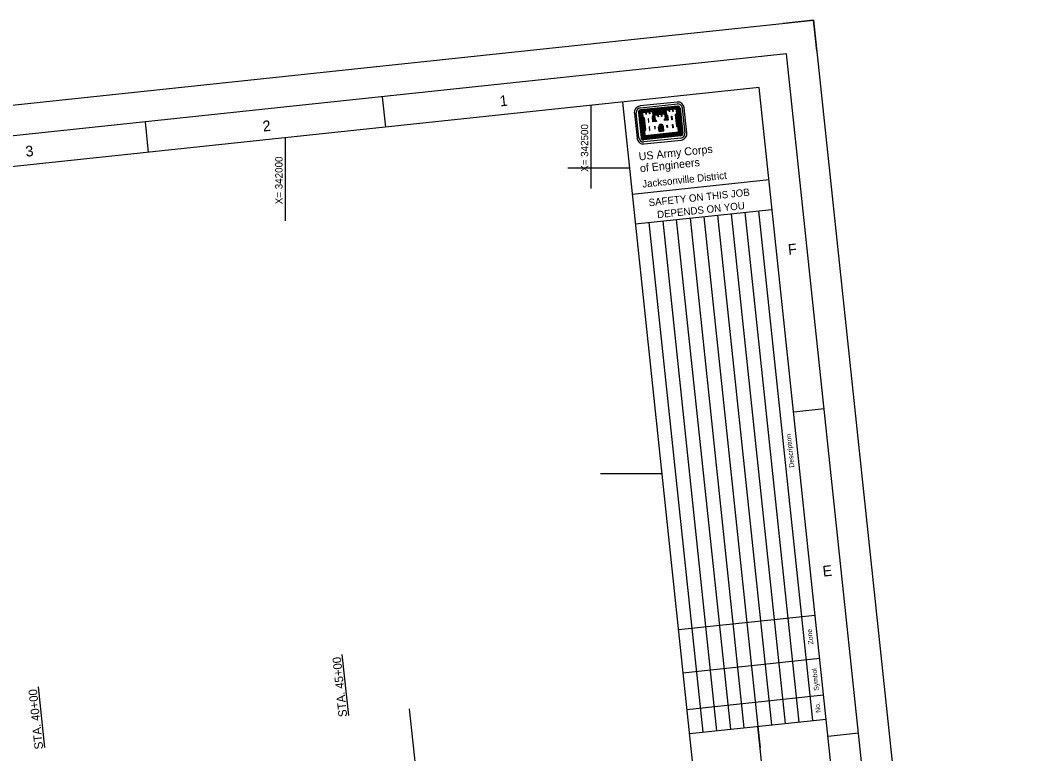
# Model space of a CAD drawing. Extents: x 338488 to 343222, y 1183896 to 1187741.
# Drawn here: x 341566 to 343222, y 1186542 to 1187741 of the extents above; entities that cross this region are included whole.
import ezdxf

# ---------------------------------------------------------------- set-up
doc = ezdxf.new("R2010")
doc.units = 0
for name, color, linetype in [('G-ANNO-NPLT', 7, 'Continuous'), ('G-ANNO-TEXT-LOGO', 7, 'Continuous'), ('G-ANNO-TEXT-TTLB', 7, 'Continuous'), ('G-ANNO-TTLB', 7, 'Continuous'), ('V-ALGN-TEXT', 7, 'Continuous'), ('V-ANNO-MATC', 7, 'Continuous'), ('V-TOPO-COOR-STAT', 7, 'Continuous')]:
    doc.layers.add(name, color=color, linetype=linetype)

msp = doc.modelspace()

# ---------------------------------------------------------------- linework, layer by layer
at = {"layer": 'G-ANNO-NPLT'}
msp.add_lwpolyline([(338488.3, 1187277.4), (342863.7, 1187741.2), (343222.1, 1184360.2), (338846.6, 1183896.4)], close=True, dxfattribs=at)
msp.add_lwpolyline([(342869, 1187691.5), (342863.7, 1187741.2), (342814, 1187736)], dxfattribs=at)
at = {"layer": 'G-ANNO-TEXT-LOGO'}
for p, q in [((342640.4, 1187607.6), (342580, 1187601.2)), ((342580.3, 1187598), (342640.8, 1187604.4)), ((342641.1, 1187601), (342580.7, 1187594.6)), ((342641.2, 1187600.1), (342580.8, 1187593.7)), ((342641.3, 1187599.2), (342580.9, 1187592.8)), ((342641.4, 1187598.4), (342580.9, 1187592)), ((342641.5, 1187597.5), (342581, 1187591.1)), ((342602.1, 1187592.5), (342620.6, 1187594.5)), ((342640.4, 1187596.8), (342644.6, 1187557.2)), ((342641.2, 1187596.9), (342645.5, 1187556.4)), ((342642.1, 1187597), (342646.4, 1187556.2)), ((342643, 1187597.1), (342647.3, 1187556.3)), ((342643.7, 1187597.2), (342648.1, 1187556.4)), ((342644.6, 1187597.3), (342649, 1187556.5)), ((342645.5, 1187597.3), (342649.9, 1187556.6)), ((342648.9, 1187597.7), (342653.2, 1187556.9)), ((342656.5, 1187557.3), (342652.2, 1187598.1)), ((342570.5, 1187589.4), (342574.8, 1187548.6)), ((342578, 1187549), (342573.6, 1187589.7)), ((342577.1, 1187590.1), (342581.4, 1187549.3)), ((342578, 1187590.2), (342582.3, 1187549.4)), ((342578.8, 1187590.3), (342583.1, 1187549.5)), ((342579.7, 1187590.4), (342584, 1187549.6)), ((342580.6, 1187590.5), (342584.9, 1187549.7)), ((342581.5, 1187590.6), (342585.8, 1187550.1)), ((342582.3, 1187590.6), (342586.5, 1187551.1)), ((342583.9, 1187582.1), (342586.1, 1187561.2)), ((342584.9, 1187581.3), (342586.9, 1187562.3)), ((342602.2, 1187591.6), (342620.7, 1187593.6)), ((342602.3, 1187590.9), (342620.8, 1187592.8)), ((342602.4, 1187590), (342620.9, 1187591.9)), ((342602.5, 1187589.1), (342621, 1187591)), ((342602.6, 1187588.3), (342621.1, 1187590.2)), ((342602.6, 1187587.4), (342621.1, 1187589.3)), ((342639.8, 1187587.1), (342641.8, 1187568.1)), ((342640.6, 1187588), (342642.8, 1187567.3)), ((342610.9, 1187559.6), (342610.2, 1187566.3)), ((342611.7, 1187559.7), (342611, 1187566.3)), ((342612.6, 1187559.8), (342611.9, 1187566.4)), ((342613.5, 1187559.9), (342612.8, 1187566.5)), ((342614.3, 1187559.9), (342613.6, 1187566.6)), ((342615.5, 1187560.1), (342614.8, 1187566.7)), ((342616.3, 1187560.2), (342615.6, 1187566.8)), ((342617.2, 1187560.3), (342616.5, 1187566.9)), ((342618.1, 1187560.3), (342617.4, 1187567)), ((342618.9, 1187560.4), (342618.2, 1187567.1)), ((342645.9, 1187555.6), (342585.5, 1187549.1)), ((342646, 1187554.8), (342585.6, 1187548.4)), ((342646.1, 1187553.9), (342585.7, 1187547.5)), ((342645.5, 1187556.4), (342585.8, 1187550.1)), ((342646.2, 1187553), (342585.8, 1187546.6)), ((342646.3, 1187552.2), (342585.8, 1187545.8)), ((342646.7, 1187548.7), (342586.2, 1187542.3)), ((342644.6, 1187557.2), (342586.5, 1187551.1)), ((342586.6, 1187539), (342647, 1187545.4)), ((342610.9, 1187559.6), (342618.9, 1187560.4))]:
    msp.add_line(p, q, dxfattribs=at)
for points in [[(342583, 1187590.7), (342583.8, 1187582.9), (342585.7, 1187581.4), (342587.7, 1187562.4), (342586.2, 1187560.4), (342587.1, 1187551.7), (342643.8, 1187557.7), (342642.9, 1187566.4), (342640.9, 1187568), (342638.9, 1187587), (342640.5, 1187588.9), (342639.7, 1187596.7), (342632.2, 1187595.9), (342626.4, 1187595.3), (342621.1, 1187594.8), (342621.9, 1187586.9), (342624, 1187585.4), (342624.7, 1187578.4), (342620.5, 1187578), (342620.5, 1187578.7), (342622.1, 1187580.7), (342621.2, 1187588.4), (342613.8, 1187587.6), (342608, 1187587), (342602.7, 1187586.5), (342603.6, 1187578.7), (342605.5, 1187577.1), (342605.6, 1187576.4), (342601.4, 1187576), (342600.7, 1187582.9), (342602.3, 1187584.8), (342601.5, 1187592.7), (342594, 1187591.9), (342588.3, 1187591.3), (342583, 1187590.7)], [(342583.9, 1187589.9), (342584.6, 1187583.3), (342586.6, 1187581.7), (342588.6, 1187562.1), (342587, 1187560.1), (342587.8, 1187552.7), (342642.9, 1187558.6), (342642.1, 1187565.9), (342640.1, 1187567.5), (342638, 1187587.2), (342639.7, 1187589.2), (342639, 1187595.7), (342633.6, 1187595.2), (342633.9, 1187592.1), (342633.4, 1187592), (342633.1, 1187595.1), (342627.8, 1187594.6), (342628.2, 1187591.5), (342627.8, 1187591.4), (342627.4, 1187594.5), (342622.1, 1187594), (342622.8, 1187587.4), (342624.7, 1187585.8), (342625.6, 1187577.7), (342619.8, 1187577.1), (342619.6, 1187579), (342621.2, 1187581), (342620.5, 1187587.6), (342615.2, 1187587), (342615.5, 1187583.9), (342615.1, 1187583.9), (342614.8, 1187586.9), (342609.4, 1187586.4), (342609.7, 1187583.3), (342609.2, 1187583.2), (342608.9, 1187586.3), (342603.6, 1187585.8), (342604.3, 1187579.2), (342606.3, 1187577.6), (342606.5, 1187575.7), (342600.7, 1187575.1), (342599.9, 1187583.2), (342601.5, 1187585.1), (342600.8, 1187591.7), (342595.5, 1187591.1), (342595.8, 1187588.1), (342595.3, 1187588), (342595, 1187591.1), (342589.6, 1187590.5), (342590, 1187587.4), (342589.6, 1187587.4), (342589.2, 1187590.5), (342583.9, 1187589.9)], [(342593.2, 1187580.1), (342593.8, 1187574.4), (342594.4, 1187574.4), (342593.8, 1187580.2), (342593.2, 1187580.1)], [(342602.1, 1187583.2), (342601.6, 1187582.6), (342602.2, 1187577), (342604.1, 1187577.2), (342602.7, 1187578.3), (342602.2, 1187583.3)], [(342622.6, 1187585.4), (342623.1, 1187584.9), (342623.7, 1187579.2), (342621.9, 1187579.1), (342623, 1187580.5), (342622.5, 1187585.4)], [(342631.8, 1187584.2), (342632.5, 1187578.5), (342632, 1187578.4), (342631.3, 1187584.2), (342631.8, 1187584.2)], [(342594.6, 1187566.9), (342595.2, 1187561), (342595.8, 1187561.1), (342595.2, 1187567), (342594.6, 1187566.9)], [(342603.7, 1187567.9), (342604.1, 1187563.8), (342604.6, 1187563.9), (342604.2, 1187567.9), (342603.7, 1187567.9)], [(342624.2, 1187570), (342624.6, 1187566), (342624.1, 1187565.9), (342623.7, 1187570), (342624.2, 1187570)], [(342633.2, 1187571), (342633.9, 1187565.1), (342633.4, 1187565.1), (342632.7, 1187571), (342633.2, 1187571)]]:
    msp.add_lwpolyline(points, dxfattribs=at)
for centre, major_axis, start_param, end_param in [((342581.1, 1187590.5), (10.7, 1.1), 1.57078, 3.141576), ((342581.1, 1187590.5), (7.45, 0.79), 1.57078, 3.141576), ((342581.1, 1187590.5), (4, 0.42), 1.57078, 3.141576), ((342641.5, 1187596.9), (10.7, 1.1), 6.283169, 7.853965), ((342641.5, 1187596.9), (7.45, 0.79), 6.28317, 7.853966), ((342641.5, 1187596.9), (4, 0.42), 6.283169, 7.853965), ((342641.5, 1187596.9), (3.13, 0.33), 6.283169, 7.853965), ((342641.5, 1187596.9), (2.27, 0.24), 6.283169, 7.853965), ((342641.5, 1187596.9), (1.41, 0.15), 6.283169, 7.853965), ((342641.5, 1187596.9), (0.543, 0.058), 6.283169, 7.853965), ((342581.1, 1187590.5), (3.13, 0.33), 1.57078, 3.141576), ((342581.1, 1187590.5), (2.27, 0.24), 1.57078, 3.141576), ((342581.1, 1187590.5), (1.41, 0.15), 1.57078, 3.141576), ((342581.1, 1187590.5), (0.543, 0.058), 1.57078, 3.141576), ((342615.7, 1187566.4), (-5.52, -0.59), 4.985832, 6.214359), ((342615.7, 1187566.4), (-4.66, -0.49), 4.947465, 6.21436), ((342615.7, 1187566.4), (-3.8, -0.4), 4.947465, 6.21436), ((342615.7, 1187566.4), (-2.93, -0.31), 4.947465, 6.21436), ((342612.7, 1187566.1), (2.07, 0.22), 0.068794, 1.335689), ((342612.7, 1187566.1), (2.93, 0.31), 0.068794, 1.335689), ((342612.7, 1187566.1), (3.8, 0.4), 0.068795, 1.335689), ((342612.7, 1187566.1), (4.66, 0.49), 0.068795, 1.335689), ((342615.7, 1187566.4), (-2.07, -0.22), 4.947465, 6.214359), ((342612.7, 1187566.1), (5.52, 0.59), 0.068795, 1.29842), ((342585.4, 1187549.7), (-10.7, -1.1), 6.28317, 7.853966), ((342585.4, 1187549.7), (-7.45, -0.79), 6.28317, 7.853966), ((342585.4, 1187549.7), (-4, -0.42), 6.28317, 7.853966), ((342585.4, 1187549.7), (-3.13, -0.33), 6.28317, 7.853966), ((342585.4, 1187549.7), (-2.27, -0.24), 6.28317, 7.853966), ((342585.4, 1187549.7), (-1.41, -0.15), 6.28317, 7.853966), ((342585.4, 1187549.7), (-0.543, -0.058), 6.28317, 7.853966), ((342645.8, 1187556.1), (0.543, 0.058), 4.712373, 6.28317), ((342645.8, 1187556.1), (1.41, 0.15), 4.712373, 6.28317), ((342645.8, 1187556.1), (2.27, 0.24), 4.712373, 6.28317), ((342645.8, 1187556.1), (4, 0.42), 4.712373, 6.28317), ((342645.8, 1187556.1), (3.13, 0.33), 4.712373, 6.28317), ((342645.8, 1187556.1), (-7.45, -0.79), 1.570781, 3.141577), ((342645.8, 1187556.1), (10.7, 1.1), 4.712373, 6.28317)]:
    msp.add_ellipse(centre, major_axis=major_axis, ratio=0.99964, start_param=start_param, end_param=end_param, dxfattribs=at)
at = {"layer": 'G-ANNO-TTLB'}
for p, q in [((342158, 1187616.1), (342163.3, 1187566.4)), ((342551, 1187607.5), (342888.4, 1184425.4)), ((341770.2, 1187575), (341775.4, 1187525.3)), ((342567, 1187457.1), (342790.8, 1187480.9)), ((342571.6, 1187408.2), (342795.3, 1187431.9)), ((342773.4, 1187429.6), (342861.7, 1186596.4)), ((342616.8, 1187413), (342705.1, 1186579.8)), ((342639.1, 1187415.4), (342727.5, 1186582.1)), ((342661.5, 1187417.8), (342749.8, 1186584.5)), ((342683.9, 1187420.1), (342772.2, 1186586.9)), ((342706.3, 1187422.5), (342794.6, 1186589.3)), ((342728.6, 1187424.9), (342817, 1186591.6)), ((342751, 1187427.3), (342839.3, 1186594)), ((342594.4, 1187410.6), (342682.7, 1186577.4)), ((342880.8, 1187106), (342831.1, 1187100.7)), ((342642.5, 1186745.1), (342866.2, 1186768.8)), ((342650, 1186674.4), (342873.7, 1186698.1)), ((342656.3, 1186614.7), (342880.1, 1186638.4)), ((342660.5, 1186575.1), (342884.3, 1186598.8)), ((342862.3, 1185732.1), (342772.4, 1186586.9)), ((342772.4, 1186586.9), (342776.1, 1186551.7)), ((342937, 1186575.7), (342887.3, 1186570.4))]:
    msp.add_line(p, q, dxfattribs=at)
for points in [[(338891.1, 1183951.4), (343167.1, 1184404.6), (342819.3, 1187686.2), (338543.3, 1187233)], [(342774.8, 1187631.3), (338672.8, 1187196.4), (339010.1, 1184014.3), (343112.1, 1184449.1)]]:
    msp.add_lwpolyline(points, close=True, dxfattribs=at)
at = {"layer": 'V-ALGN-TEXT'}
for p, q in [((342103.3, 1186604.8), (342092.8, 1186704.2)), ((341606.1, 1186552.1), (341595.6, 1186651.5))]:
    msp.add_line(p, q, dxfattribs=at)
at = {"layer": 'V-ANNO-MATC'}
msp.add_line((342339.8, 1185322.5), (342202.8, 1186615.3), dxfattribs=at)
at = {"layer": 'V-TOPO-COOR-STAT'}
for p, q in [((342500, 1187466.4), (342500, 1187602.1)), ((342000, 1187413.4), (342000, 1187549.1)), ((342461.9, 1187500), (342562.4, 1187500)), ((342514.9, 1187000), (342615.4, 1187000))]:
    msp.add_line(p, q, dxfattribs=at)

# ---------------------------------------------------------------- texts
at = {"layer": 'G-ANNO-TEXT-TTLB'}
for s, height, rotation, p in [('US Army Corps', 13.086, 6.0506, (342578.3, 1187511.9)), ('of Engineers', 13.086, 6.0506, (342580.3, 1187492.6)), ('Jacksonville District', 11.9, 6.0506, (342584, 1187467.5)), ('SAFETY ON THIS JOB', 11.9, 6.0506, (342594.4, 1187437.1)), ('DEPENDS ON YOU', 11.9, 6.0506, (342608.3, 1187417.5)), ('Description', 8, 96.0506, (342832.2, 1187010.3)), ('Zone', 8, 96.0506, (342863.2, 1186721.3)), ('Symbol', 8, 96.0506, (342872.4, 1186645.5)), ('No.', 8, 96.0506, (342875.2, 1186609.5))]:
    msp.add_text(s, height=height, rotation=rotation, dxfattribs=at).set_placement(p)
at = {"layer": 'G-ANNO-TTLB'}
for s, p in [('1', (342351.1, 1187600.3)), ('2', (341963.4, 1187559.2)), ('3', (341575.5, 1187518)), ('F', (342822.7, 1187357.5)), ('E', (342879.3, 1186831.6))]:
    msp.add_text(s, height=17.5, rotation=6.0506, dxfattribs=at).set_placement(p)
at = {"layer": 'V-ALGN-TEXT'}
for s, p in [('STA. 45+00', (342100.7, 1186602.8)), ('STA. 40+00', (341603.5, 1186550.1))]:
    msp.add_text(s, height=13.92, rotation=96.0506, dxfattribs=at).set_placement(p)
at = {"layer": 'V-TOPO-COOR-STAT'}
for s, p in [('X= 342500', (342495, 1187493.4)), ('X= 342000', (341995, 1187440.4))]:
    msp.add_text(s, height=12, rotation=90, dxfattribs=at).set_placement(p)

doc.saveas('drawing.dxf')
